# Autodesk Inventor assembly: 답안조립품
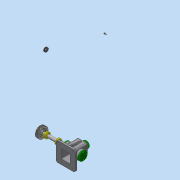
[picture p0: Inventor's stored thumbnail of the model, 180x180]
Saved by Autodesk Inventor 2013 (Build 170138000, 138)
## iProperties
Created: 2018-10
Part Number: 답안조립품
Document SubType Name: Assembly
Designer: Administrator
Author: Administrator
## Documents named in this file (14)
- C:\Users\Administrator\Desktop\481013V1007\답안조립품.iam
- C:\Users\Administrator\Desktop\481013V1007\본체.ipt
- C:\Users\Administrator\Desktop\481013V1007\V-벨트풀리.ipt
- C:\Users\Administrator\Desktop\481013V1007\뒤커버.ipt
- C:\Users\Administrator\Desktop\481013V1007\멈춤링 15 x 1.ipt
- C:\Users\Administrator\Desktop\481013V1007\베어링 15 x 35 x 11.ipt
- C:\Users\Administrator\Desktop\481013V1007\볼트 M4 x 10.ipt
- C:\Users\Administrator\Desktop\481013V1007\볼트 M6 x 12.ipt
- C:\Users\Administrator\Desktop\481013V1007\상부캡.ipt
- C:\Users\Administrator\Desktop\481013V1007\앞커버.ipt
- C:\Users\Administrator\Desktop\481013V1007\오일실 15 25 7.ipt
- C:\Users\Administrator\Desktop\481013V1007\와셔.ipt
- C:\Users\Administrator\Desktop\481013V1007\축.ipt
- C:\Users\Administrator\Desktop\481013V1007\키 5 x 5 x 14.ipt
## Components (1 placed, 1 different names)
1. V-벨트풀리:1 — 플러쉬:1
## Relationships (1: Flush 1)
- 플러쉬:1 [Flush]: V-벨트풀리:1
